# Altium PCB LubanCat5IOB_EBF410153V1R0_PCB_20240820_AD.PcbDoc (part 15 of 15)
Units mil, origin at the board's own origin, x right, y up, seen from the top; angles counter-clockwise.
Board outline 6811.02 x 4055.12 mil, 6 copper layers (TOP, GND02, ART03, ART04, PWR05, BOTTOM), stack 59.279 mil thick; 981 components, 783 nets, 3627 pads, 2669 vias.
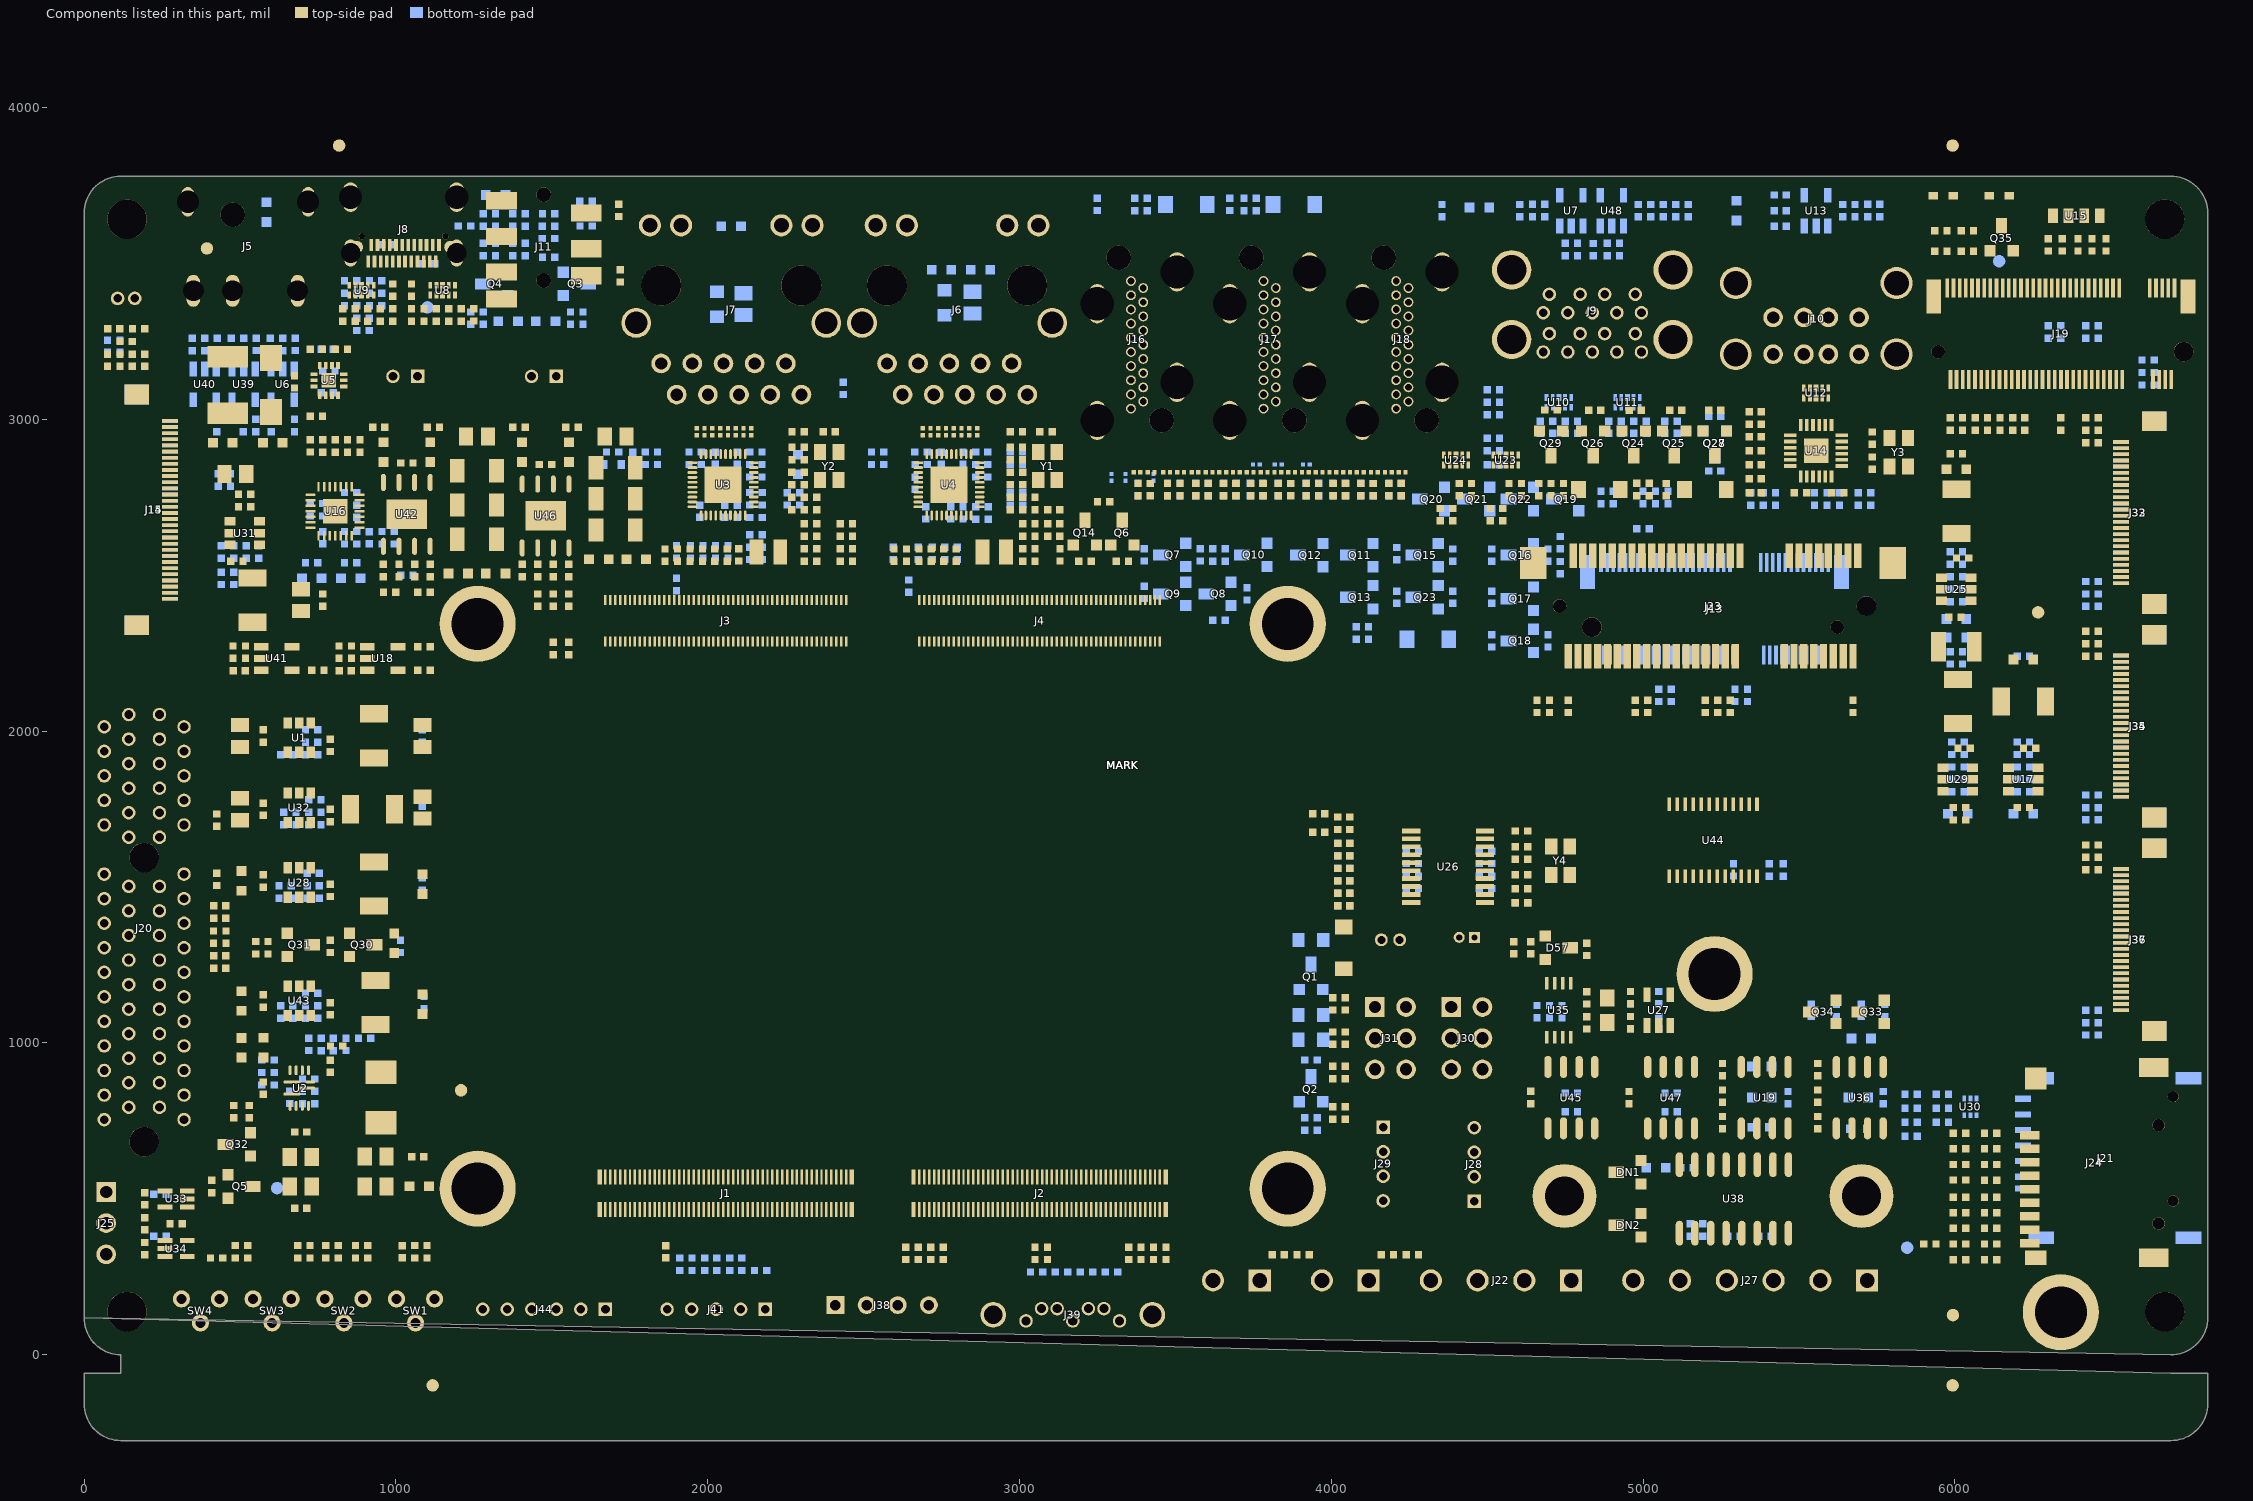
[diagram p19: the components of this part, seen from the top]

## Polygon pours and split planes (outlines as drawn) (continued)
GND on TOP "TOP-GND 38" (solid, pour order 208): 2952,2969 2952,2734 3066,2734 3077,2723 3077,2605 3069,2597 3038,2597 3038,2533 3092,2533 3103,2544 3103,2723 3114,2734 3178,2734 3178,2969 2952,2969
VCC_5V0_S0 on TOP "TOP-VCC_5V0_S0 3" (solid, pour order 86): 6372,2413.37 6372,2315.37 6380,2307.37 6432,2307.37 6432,2358.37 6436,2362.37 6447,2362.37 6451,2366.37 6451,2413.37 6446,2418.37 6377,2418.37 6372,2413.37
GND on TOP "TOP-GND 39" (solid, pour order 205): 19 vertices, not listed, extent 4786,982 5074,1268
GND on TOP "TOP-GND 40" (solid, pour order 256): 30 vertices, not listed, extent 20,3156 817,3759.53
N16606404 on TOP "TOP-N16606404" (solid, pour order 75): 2843,2698 2849,2698 2853,2694 2853,2682 2857,2678 2870,2678 2874,2674 2874,2645 2903,2616 2903,2535 2859,2535 2859,2606 2840,2625 2840,2695 2843,2698
VDD_LCD0_3V3 on TOP "TOP-VDD_LCD0_3V3" (solid, pour order 172): 310,3273 344,3273 352,3265 352,3165 376,3141 376,2922 365,2911 311,2911 311,3099 302,3108 302,3265 310,3273
VDD_CAM2_5V on TOP "TOP-VDD_CAM2_5V" (solid, pour order 110): 6559,2197 6508,2197 6508,2218 6498,2228 6448,2228 6448,2260 6439,2269 6408,2269 6408,2293 6550,2293 6559,2284 6559,2197
VCC_12V on TOP "TOP-VCC_12V 5" (solid, pour order 156): 19 vertices, not listed, extent 439,863.37 694,968.37
GND on TOP "TOP-GND 41" (solid, pour order 276): 56 vertices, not listed, extent 5591,286 6458,2440
GND on TOP "TOP-GND 42" (solid, pour order 271): 61 vertices, not listed, extent 713,2571 1834,3408
GND on TOP "TOP-GND 43" (solid, pour order 273): 37 vertices, not listed, extent 5854,20 6791.02,3535.37
VCC_5V0_S0 on TOP "TOP-VCC_5V0_S0 4" (solid, pour order 189): 22 vertices, not listed, extent 495,2259 1030,2412
GND on TOP "TOP-GND 44" (solid, pour order 146): 50 vertices, not listed, extent 6440,1622.37 6512,1857.37
VCC_12V on TOP "TOP-VCC_12V 6" (solid, pour order 137): 82 vertices, not listed, extent 393,437.37 538,532.37
GND on TOP "TOP-GND 45" (solid, pour order 193): 82 vertices, not listed, extent 1546,411 1761,618
GND on TOP "TOP-GND 46" (solid, pour order 160): 907,3451.37 885,3451.37 857,3479.37 827,3479.37 817,3489.37 817,3619.37 840,3642.37 924,3642.37 932,3634.37 932,3476.37 907,3451.37
GND on TOP "TOP-GND 47" (solid, pour order 167): 676,1809.37 676,1896.37 686,1906.37 847,1906.37 856,1897.37 856,1848.37 848,1840.37 832,1840.37 825,1833.37 825,1805.37 794,1774.37 711,1774.37 676,1809.37
GND on TOP "TOP-GND 48" (solid, pour order 258): 25 vertices, not listed, extent 4908,965 5578,2042
N16783872 on TOP "TOP-N16783872" (solid, pour order 77): 82 vertices, not listed, extent 4900,2738.37 4994,2809.37
VDD_LCD1_3V3 on TOP "TOP-VDD_LCD1_3V3" (solid, pour order 123): 592,2259 592,2296 576,2312 383,2312 375,2304 375,2261 383,2253 459,2253 465,2259 592,2259
N17141824 on TOP "TOP-N17141824 1" (solid, pour order 48): 82 vertices, not listed, extent 1485,2839 1518,2974
VCC_12V on TOP "TOP-VCC_12V 7" (solid, pour order 102): 82 vertices, not listed, extent 770,1234.37 890,1314.37
GND on TOP "TOP-GND 49" (solid, pour order 226): 25 vertices, not listed, extent 3070,607 3985,1701
GND on TOP "TOP-GND 50" (solid, pour order 182): 69 vertices, not listed, extent 514,1162.37 757,1313.37
N16835491 on TOP "TOP-N16835491" (solid, pour order 31): 82 vertices, not listed, extent 712,1448.37 808,1486.37
N16935675 on TOP "TOP-N16935675" (solid, pour order 25): 6248,1957 6248,1869 6285,1869 6285,1951 6279,1957 6248,1957
VCC12V_PCIEX4 on TOP "TOP-VCC12V_PCIEX4 1" (solid, pour order 187): 30 vertices, not listed, extent 121,1906 348,2082
VCCA_3V3_S0 on TOP "TOP-VCCA_3V3_S0" (solid, pour order 84): 1775,434 1775,400 1755,380 1589,380 1565,404 1520,404 1515,399 1515,383 1522,376 1559,376 1579,356 1760,356 1788,384 1788,434 1775,434
GND on TOP "TOP-GND 51" (solid, pour order 181): 378,2968 378,2720 390,2708 507,2708 507,2770 487,2790 487,2946 465,2968 378,2968
GND on TOP "TOP-GND 52" (solid, pour order 149): 82 vertices, not listed, extent 4001,1280 4117,1420
N16892339 on TOP "TOP-N16892339" (solid, pour order 30): 82 vertices, not listed, extent 712,1688.37 805,1726.37
VCC5V0_HDMI_RX on TOP "TOP-VCC5V0_HDMI_RX" (solid, pour order 93): 4817,2889.37 4817,2746.37 4811,2740.37 4737,2740.37 4733,2744.37 4733,2766.37 4764,2766.37 4769,2771.37 4769,2874.37 4760,2883.37 4760,2890.37 4765,2895.37 4811,2895.37 4817,2889.37
SATA_5V0 on TOP "TOP-SATA_5V0 1" (solid, pour order 85): 90 vertices, not listed, extent 1152,279 1255,366
N16891638 on TOP "TOP-N16891638" (solid, pour order 33): 82 vertices, not listed, extent 712,1913.37 806,1952.37
GND on TOP "TOP-GND 53" (solid, pour order 247): 29 vertices, not listed, extent 3027,1471 4617,2413
VCC_1V8_S3 on TOP "TOP-VCC_1V8_S3" (solid, pour order 100): 1522,316 1789,316 1809,336 1809,434 1818,434 1818,310 1797,289 1522,289 1516,295 1516,310 1522,316
VCC_12V on TOP "TOP-VCC_12V 8" (solid, pour order 155): 471,1761.37 471,1852.37 482,1863.37 655,1863.37 666,1852.37 666,1784.37 610,1784.37 587,1761.37 471,1761.37
GND on TOP "TOP-GND 54" (solid, pour order 203): 17 vertices, not listed, extent 447,1542.37 828,1742.37
VCC_5V0_S0 on TOP "TOP-VCC_5V0_S0 5" (solid, pour order 38): 82 vertices, not listed, extent 1595,2526 1655,2592
GND on TOP "TOP-GND 55" (solid, pour order 176): 68 vertices, not listed, extent 6003,2214.37 6208,2378.37
GND on TOP "TOP-GND 56" (solid, pour order 212): 25 vertices, not listed, extent 2256,1901 2548,2303
VCC3V3_PCIEX4 on TOP "TOP-VCC3V3_PCIEX4 1" (solid, pour order 185): 72 vertices, not listed, extent 26,1672.37 274,1836.37
GND on TOP "TOP-GND 57" (solid, pour order 200): 82 vertices, not listed, extent 6570,1840.37 6693,2267.37
VCC_12V on TOP "TOP-VCC_12V 9" (solid, pour order 204): 31 vertices, not listed, extent 395,2659 636,3065
VCC_1V8_S0 on TOP "TOP-VCC_1V8_S0" (solid, pour order 121): 1522,279 1802,279 1824,301 1824,434 1837,434 1837,271 1815,249 1522,249 1516,255 1516,273 1522,279
VCC3V3_PCIECLK on TOP "TOP-VCC3V3_PCIECLK" (solid, pour order 66): 4948,1153 4948,1205 4956,1213 5017,1213 5025,1205 5025,1131 4997,1131 4975,1153 4948,1153
1V05_PHY0 on TOP "TOP-1V05_PHY0" (solid, pour order 112): 2935,2535 3022,2535 3022,2604 3031,2613 3062,2613 3062,2637 2942,2637 2935,2630 2935,2535
GND on TOP "TOP-GND 58" (solid, pour order 23): 1676,2303 1621,2303 1611,2293 1611,2263 1622,2252 1670,2252 1676,2258 1676,2303
VCC_3V3_S0 on TOP "TOP-VCC_3V3_S0 3" (solid, pour order 57): 82 vertices, not listed, extent 5216,2744 5294,2805
VCC_12V on TOP "TOP-VCC_12V 10" (solid, pour order 32): 82 vertices, not listed, extent 1319,2464 1378,2526
GND on TOP "TOP-GND 59" (solid, pour order 221): 36 vertices, not listed, extent 6203,2430 6500,2816
VCC_12V on TOP "TOP-VCC_12V 11" (solid, pour order 134): 471,1997.37 471,2061.37 481,2071.37 657,2071.37 667,2061.37 667,2008.37 598,2008.37 587,1997.37 471,1997.37
VCC_3V3_S3 on TOP "TOP-VCC_3V3_S3 2" (solid, pour order 78): 82 vertices, not listed, extent 611,2250 722,2312
N17085653 on TOP "TOP-N17085653" (solid, pour order 28): 82 vertices, not listed, extent 712,1069.37 806,1106.37
VCC5V0_USB_S0 on TOP "TOP-VCC5V0_USB_S0" (solid, pour order 173): 885,1941.37 1042,1941.37 1056,1955.37 1056,1972.37 1127,1972.37 1133,1966.37 1133,1865.37 1127,1859.37 895,1859.37 885,1869.37 885,1941.37
GND on TOP "TOP-GND 60" (solid, pour order 143): 487,1513 487,1384 600,1384 600,1513 487,1513
VCC_5V0_S0 on TOP "TOP-VCC_5V0_S0 6" (solid, pour order 60): 5025,1080 5025,1008 5017,1000 4956,1000 4948,1008 4948,1057 4992,1057 5001,1066 5001,1080 5025,1080
N16892291 on TOP "TOP-N16892291" (solid, pour order 127): 676,1819.37 676,1748.37 687,1737.37 819,1737.37 827,1729.37 827,1704.37 882,1704.37 882,1794.37 812,1794.37 792,1774.37 711,1774.37 704,1781.37 704,1818.37 703,1819.37 676,1819.37
N16843993 on TOP "TOP-N16843993" (solid, pour order 21): 6038,1957 6038,1899 6040,1897 6040,1869 6075,1869 6075,1950 6068,1957 6038,1957
GND on TOP "TOP-GND 61" (solid, pour order 215): 37 vertices, not listed, extent 1577,2469 2482,2942
N16803397 on TOP "TOP-N16803397" (solid, pour order 26): 6033,2567 6033,2481 6035,2479 6070,2479 6070,2562 6065,2567 6033,2567
VCC_12V on TOP "TOP-VCC_12V 12" (solid, pour order 131): 5945,1822 6000,1822 6007,1815 6007,1682 5999,1674 5908,1674 5902,1680 5902,1762 5908,1768 5939,1768 5945,1774 5945,1822
GND on TOP "TOP-GND 62" (solid, pour order 265): 21 vertices, not listed, extent 3221,2915 4941,3597
VCC4V0_SYS on TOP "TOP-VCC4V0_SYS" (solid, pour order 236): 43 vertices, not listed, extent 694,442 1707,814.37
N17141731 on TOP "TOP-N17141731 1" (solid, pour order 190): 17 vertices, not listed, extent 1173,2489 1304,2975
GND on TOP "TOP-GND 63" (solid, pour order 255): 51 vertices, not listed, extent 1979,202 3238,718
N16803401 on TOP "TOP-N16803401" (solid, pour order 124): 5941,2441 6014,2441 6026,2453 6026,2597 6035,2606 6050,2606 6050,2662 5960,2662 5960,2607 5986,2607 5993,2600 5993,2474 5988,2469 5941,2469 5941,2441
SATA_12V on TOP "TOP-SATA_12V" (solid, pour order 217): 32 vertices, not listed, extent 452,51.37 687,663.37
GND on GND02 "GND02-GND" (solid, pour order 299): 82 vertices, not listed, extent 20,20 6791.02,3759.53
GND on ART03 "ART03-GND" (solid, pour order 297): 151 vertices, not listed, extent 20,801 6150,2370
VCC_1V8_S0 on ART03 "ART03-VCC_1V8_S0" (solid, pour order 4): 82 vertices, not listed, extent 2994,1276 3059,1300
GND on ART03 "ART03-GND 1" (solid, pour order 286): 44 vertices, not listed, extent 20,20 1839,1126
M2PCIE_3V3 on ART03 "ART03-M2PCIE_3V3" (solid, pour order 229): 18 vertices, not listed, extent 5937,2885.37 6700,3183.37
VCC_3V3_S3 on ART03 "ART03-VCC_3V3_S3" (solid, pour order 239): 27 vertices, not listed, extent 146,204 1433,485
GND on ART03 "ART03-GND 2" (solid, pour order 219): 43 vertices, not listed, extent 211,1884 1632,2524
VCC_3V3_S3 on ART03 "ART03-VCC_3V3_S3 1" (solid, pour order 3): 82 vertices, not listed, extent 2993,1331 3060,1354
VCC5V0_USB_S0 on ART03 "ART03-VCC5V0_USB_S0" (solid, pour order 270): 20 vertices, not listed, extent 1620,3377 5604,3739
VCC_1V8_S0 on ART03 "ART03-VCC_1V8_S0 1" (solid, pour order 207): 1500,264 1500,856 1514,870 1716,870 1729,857 1729,810 1723,804 1694,804 1677,821 1600,821 1583,804 1583,264 1575,256 1508,256 1500,264
MINIPCIE_3V3 on ART03 "ART03-MINIPCIE_3V3" (solid, pour order 228): 5948,2313 5941,2320 5867,2320 5859,2312 5859,2183 5845,2169 4834,2169 4824,2159 4824,2097 4833,2088 5931,2088 5948,2105 5948,2313
GND on ART03 "ART03-GND 3" (solid, pour order 278): 76 vertices, not listed, extent 1575,192 6649,2323
SATA_5V0 on ART03 "ART03-SATA_5V0" (solid, pour order 230): 1020,1100 1020,305 1040,285 1235,285 1243,285 1253,295 1253,400 1243,410 1235,410 1155,410 1135,430 1135,1100 1125,1110 1030,1110 1020,1100
GND on ART03 "ART03-GND 4" (solid, pour order 282): 54 vertices, not listed, extent 1632,20 6791.02,3530.37
VCC_5V0_S0 on ART03 "ART03-VCC_5V0_S0" (solid, pour order 222): 23 vertices, not listed, extent 805,2315 1658,2597
GND on ART03 "ART03-GND 5" (solid, pour order 232): 1189,3412 1189,3756 851,3756 851,3412 1189,3412
GND on ART03 "ART03-GND 6" (solid, pour order 291): 103 vertices, not listed, extent 20,2122 2549,3499.37
GND on ART03 "ART03-GND 7" (solid, pour order 287): 40 vertices, not listed, extent 4666,2993 6791.02,3759.53
VCC5V0_USB_S0 on ART03 "ART03-VCC5V0_USB_S0 1" (solid, pour order 214): 225,3333 643,3333 653,3323 653,3089 640,3076 572,3076 556,3092 556,3163 545,3174 223,3174 212,3185 212,3320 225,3333
VCC_12V on ART03 "ART03-VCC_12V" (solid, pour order 242): 31 vertices, not listed, extent 909,2459 1827,2849
GND on ART03 "ART03-GND 8" (solid, pour order 209): 26 vertices, not listed, extent 6136,2271 6703,2890
VCC12V_PCIEX4 on ART03 "ART03-VCC12V_PCIEX4" (solid, pour order 269): 24 vertices, not listed, extent 27,873 1135,2071
GND on ART03 "ART03-GND 9" (solid, pour order 296): 71 vertices, not listed, extent 2307,2030 6597,3044
VCC_12V on PWR05 "PWR05-VCC_12V" (solid, pour order 285): 31 vertices, not listed, extent 385,110.37 1712,2901
GND on PWR05 "PWR05-GND" (solid, pour order 298): 82 vertices, not listed, extent 20,20 6791.02,3759.53
VCC_3V3_S3 on PWR05 "PWR05-VCC_3V3_S3" (solid, pour order 108): 82 vertices, not listed, extent 1369,398 1575,446

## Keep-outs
Multi-Layer:
  region: 1760,3265 1760,3655 3115,3655 3115,3265 1760,3265

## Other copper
TOP:
  drawing of 162 lines, arcs and shapes, not listed
GND02:
  drawing of 1484 lines, arcs and shapes, not listed
ART03:
  drawing of 366 lines, arcs and shapes, not listed
ART04:
  drawing of 986 lines, arcs and shapes, not listed
PWR05:
  drawing of 1485 lines, arcs and shapes, not listed
BOTTOM:
  drawing of 80 lines, arcs and shapes, not listed

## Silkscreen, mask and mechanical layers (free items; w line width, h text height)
OUTLINE:
  lines w6: 118.11,0 cw(c118.11,118.11) 0,118.11 0,3661.42 cw(c118.11,3661.42) 118.11,3779.53 6692.91,3779.53 cw(c6692.91,3661.42) 6811.02,3661.42 6811.02,118.11 cw(c6692.91,118.11) 6692.91,0 ; 118.11,0 6692.91,0 ; 118.11,0 118.11,-59.05 0,-59.05 0,-157.48 ccw(c118.11,-157.48) 118.11,-275.59 6692.91,-275.59 ccw(c6692.91,-157.48) 6811.02,-157.48 6811.02,-59.05 6692.91,-59.05 6692.91,0
NCLEGEND-1-6:
  circle w1: c7815.5,681 r15.75
  lines w1: 7366,-6444 12202,-6444 ; 7366,-6194 12202,-6194 ; 7366,-5944 12202,-5944 ; 7366,-5694 12202,-5694 ; 7366,-5444 12202,-5444 ; 7366,-5194 12202,-5194 ; 7366,-4944 12202,-4944 ; 7366,-4694 12202,-4694 ; 7366,-4444 12202,-4444 ; 7366,-4194 12202,-4194 ; 7366,-3944 12202,-3944 ; 7366,-3694 12202,-3694 ; 7366,-3444 12202,-3444 ; 7366,-3194 12202,-3194 ; 7366,-2944 12202,-2944 ; 7366,-2694 12202,-2694 ; 7366,-2444 12202,-2444 ; 7366,-2194 12202,-2194 ; 7366,-1944 12202,-1944 ; 7366,-1694 12202,-1694 ; 7366,-1444 12202,-1444 ; 7366,-1194 12202,-1194 ; 7366,-944 12202,-944 ; 7366,-694 12202,-694 ; 7366,-444 12202,-444 ; 7366,-194 12202,-194 ; 7366,56 12202,56 ; 7366,306 12202,306 ; 7366,556 12202,556 ; 7366,806 12202,806 ; 7366,1056 12202,1056 ; 7366,1306 12202,1306 ; 7366,1556 12202,1556 ; 7366,1806 12202,1806 ; 7366,2056 12202,2056 ; 7366,2306 12202,2306 ; 7366,2556 12202,2556 ; 7366,2806 12202,2806 ; 7366,3056 12202,3056 ; 7366,3306 12202,3306 ; 7366,3556 12202,3556 ; 7366,3806 12202,3806 ; 7811.5,3181 7819.5,3181 ; 7815.5,3177 7815.5,3185 ; 8265,-6694 8265,3556 ; 10156,-6694 10156,3556 ; 11427,-6694 11427,3556 ; 7366,-6694 7366,4056 12202,4056 12202,-6694 7366,-6694 ; 7780.06,-6604.43 ccw(c7780.06,-6569) 7780.06,-6533.57 7850.94,-6533.57 ccw(c7850.94,-6569) 7850.94,-6604.43 7780.06,-6604.43 ; 7787.9,-6084.7 ccw(c7787.9,-6069) 7787.9,-6053.3 7843.1,-6053.3 ccw(c7843.1,-6069) 7843.1,-6084.7 7787.9,-6084.7 ; 7789.91,-6342.62 ccw(c7789.91,-6319) 7789.91,-6295.38 7841.09,-6295.38 ccw(c7841.09,-6319) 7841.09,-6342.62 7789.91,-6342.62 ; 7791.9,-5838.7 ccw(c7791.9,-5819) 7791.9,-5799.3 7839.1,-5799.3 ccw(c7839.1,-5819) 7839.1,-5838.7 7791.9,-5838.7 ; 7792.06,2181 7798.93,2164.43 7815.5,2157.56 7832.07,2164.43 7838.94,2181 7832.07,2197.57 7815.5,2204.44 7798.93,2197.57 7792.06,2181 ; 7794.83,1427.56 ccw(c7815.5,1427.56) 7836.17,1427.56 7836.17,1434.44 ccw(c7815.5,1434.44) 7794.83,1434.44 7794.83,1427.56 ; 7795.81,-5592.62 ccw(c7795.81,-5569) 7795.81,-5545.38 7835.19,-5545.38 ccw(c7835.19,-5569) 7835.19,-5592.62 7795.81,-5592.62 ; 7800.74,919.93 7800.74,942.07 7830.26,942.07 7830.26,919.93 7800.74,919.93 ; 7801.72,-5338.69 ccw(c7801.72,-5319) 7801.72,-5299.31 7829.28,-5299.31 ccw(c7829.28,-5319) 7829.28,-5338.69 7801.72,-5338.69 ; 7801.72,1167.22 7815.5,1194.78 7829.28,1167.22 7801.72,1167.22 ; 7802.7,1931 7815.5,1943.8 7828.3,1931 7815.5,1918.2 7802.7,1931 ; 7805.66,2426.08 7815.5,2421.16 7825.34,2426.08 7825.34,2435.92 7815.5,2440.84 7805.66,2435.92 7805.66,2426.08 ; 7810.5,2681 7813,2676 7818,2676 7820.5,2681 7818,2686 7813,2686 7810.5,2681 ; 7811.5,2927 7819.5,2927 7819.5,2935 7811.5,2935 7811.5,2927 ; 7812.06,1660.33 ccw(c7812.06,1681) 7812.06,1701.67 7818.94,1701.67 ccw(c7818.94,1681) 7818.94,1660.33 7812.06,1660.33
  text "DRILL CHART: TOP to BOTTOM" at 8484,3868.5 h125
  text "ALL UNITS ARE IN MILS" at 8734,3618.5 h125
  text "FIGURE" at 7515.5,3368.5 h125
  text "SIZE" at 9010.5,3368.5 h125
  text "PLATED" at 10491.5,3368.5 h125
  text "QTY" at 11664.5,3368.5 h125
  text "8.0" at 9060.5,3118.5 h125
  text "PLATED" at 10491.5,3118.5 h125
  text "308" at 11664.5,3118.5 h125
  text "8.0" at 9060.5,2868.5 h125
  text "PLATED" at 10491.5,2868.5 h125
  text "2357" at 11614.5,2868.5 h125
  text "10.0" at 9010.5,2618.5 h125
  text "PLATED" at 10491.5,2618.5 h125
  text "4" at 11764.5,2618.5 h125
  text "19.685" at 8910.5,2368.5 h125
  text "PLATED" at 10491.5,2368.5 h125
  text "2" at 11764.5,2368.5 h125
  text "21.654" at 8910.5,2118.5 h125
  text "PLATED" at 10491.5,2118.5 h125
  text "57" at 11714.5,2118.5 h125
  text "25.591" at 8910.5,1868.5 h125
  text "PLATED" at 10491.5,1868.5 h125
  text "2" at 11764.5,1868.5 h125
  text "27.559" at 8910.5,1618.5 h125
  text "PLATED" at 10491.5,1618.5 h125
  text "18" at 11714.5,1618.5 h125
  text "27.559" at 8910.5,1368.5 h125
  text "PLATED" at 10491.5,1368.5 h125
  text "25" at 11714.5,1368.5 h125
  text "27.559" at 8910.5,1118.5 h125
  text "PLATED" at 10491.5,1118.5 h125
  text "64" at 11714.5,1118.5 h125
  text "29.528" at 8910.5,868.5 h125
  text "PLATED" at 10491.5,868.5 h125
  text "7" at 11764.5,868.5 h125
  text "31.496" at 8910.5,618.5 h125
  text "PLATED" at 10491.5,618.5 h125
  text "12" at 11714.5,618.5 h125
  text "33.465" at 8910.5,368.5 h125
  text "PLATED" at 10491.5,368.5 h125
  text "4" at 11764.5,368.5 h125
  text "39.37" at 8960.5,118.5 h125
  text "PLATED" at 10491.5,118.5 h125
  text "32" at 11714.5,118.5 h125
  text "39.37" at 8960.5,-131.5 h125
  text "PLATED" at 10491.5,-131.5 h125
  text "3" at 11764.5,-131.5 h125
  text "39.37" at 8960.5,-381.5 h125
  text "PLATED" at 10491.5,-381.5 h125
  text "8" at 11764.5,-381.5 h125
  text "47.244" at 8910.5,-631.5 h125
  text "PLATED" at 10491.5,-631.5 h125
  text "22" at 11714.5,-631.5 h125
  text "59.055" at 8910.5,-881.5 h125
  text "PLATED" at 10491.5,-881.5 h125
  text "2" at 11764.5,-881.5 h125
  text "72.047" at 8910.5,-1131.5 h125
  text "PLATED" at 10491.5,-1131.5 h125
  text "4" at 11764.5,-1131.5 h125
  text "78.74" at 8960.5,-1381.5 h125
  text "PLATED" at 10491.5,-1381.5 h125
  text "4" at 11764.5,-1381.5 h125
  text "94.5" at 9010.5,-1631.5 h125
  text "PLATED" at 10491.5,-1631.5 h125
  text "4" at 11764.5,-1631.5 h125
  text "125.98" at 8910.5,-1881.5 h125
  text "PLATED" at 10491.5,-1881.5 h125
  text "2" at 11764.5,-1881.5 h125
  text "166.142" at 8860.5,-2131.5 h125
  text "PLATED" at 10491.5,-2131.5 h125
  text "6" at 11764.5,-2131.5 h125
  text "19.685" at 8910.5,-2381.5 h125
  text "NON-PLATED" at 10291.5,-2381.5 h125
  text "2" at 11764.5,-2381.5 h125
  text "35.433" at 8910.5,-2631.5 h125
  text "NON-PLATED" at 10291.5,-2631.5 h125
  text "2" at 11764.5,-2631.5 h125
  text "39.37" at 8960.5,-2881.5 h125
  text "NON-PLATED" at 10291.5,-2881.5 h125
  text "2" at 11764.5,-2881.5 h125
  text "43.307" at 8910.5,-3131.5 h125
  text "NON-PLATED" at 10291.5,-3131.5 h125
  text "1" at 11764.5,-3131.5 h125
  text "43.307" at 8910.5,-3381.5 h125
  text "NON-PLATED" at 10291.5,-3381.5 h125
  text "2" at 11764.5,-3381.5 h125
  text "47.244" at 8910.5,-3631.5 h125
  text "NON-PLATED" at 10291.5,-3631.5 h125
  text "2" at 11764.5,-3631.5 h125
  text "62.992" at 8910.5,-3881.5 h125
  text "NON-PLATED" at 10291.5,-3881.5 h125
  text "2" at 11764.5,-3881.5 h125
  text "62.992" at 8910.5,-4131.5 h125
  text "NON-PLATED" at 10291.5,-4131.5 h125
  text "1" at 11764.5,-4131.5 h125
  text "78.701" at 8910.5,-4381.5 h125
  text "NON-PLATED" at 10291.5,-4381.5 h125
  text "7" at 11764.5,-4381.5 h125
  text "94.488" at 8910.5,-4631.5 h125
  text "NON-PLATED" at 10291.5,-4631.5 h125
  text "2" at 11764.5,-4631.5 h125
  text "125.984" at 8860.5,-4881.5 h125
  text "NON-PLATED" at 10291.5,-4881.5 h125
  text "4" at 11764.5,-4881.5 h125
  text "127.953" at 8860.5,-5131.5 h125
  text "NON-PLATED" at 10291.5,-5131.5 h125
  text "4" at 11764.5,-5131.5 h125
  text "47.244x19.685" at 8560.5,-5381.5 h125
  text "PLATED" at 10491.5,-5381.5 h125
  text "2" at 11764.5,-5381.5 h125
  text "62.992x23.622" at 8560.5,-5631.5 h125
  text "PLATED" at 10491.5,-5631.5 h125
  text "2" at 11764.5,-5631.5 h125
  text "66.902x19.701" at 8560.5,-5881.5 h125
  text "PLATED" at 10491.5,-5881.5 h125
  text "3" at 11764.5,-5881.5 h125
  text "70.902x15.701" at 8560.5,-6131.5 h125
  text "PLATED" at 10491.5,-6131.5 h125
  text "2" at 11764.5,-6131.5 h125
  text "74.803x23.622" at 8560.5,-6381.5 h125
  text "PLATED" at 10491.5,-6381.5 h125
  text "2" at 11764.5,-6381.5 h125
  text "106.299x35.429" at 8510.5,-6631.5 h125
  text "PLATED" at 10491.5,-6631.5 h125
  text "12" at 11714.5,-6631.5 h125
DRAWING_ORIGIN:
  lines w1: -25,0 25,0 ; 0,-25 0,25
Mechanical 255:
  drawing of 168 lines, arcs and shapes, not listed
